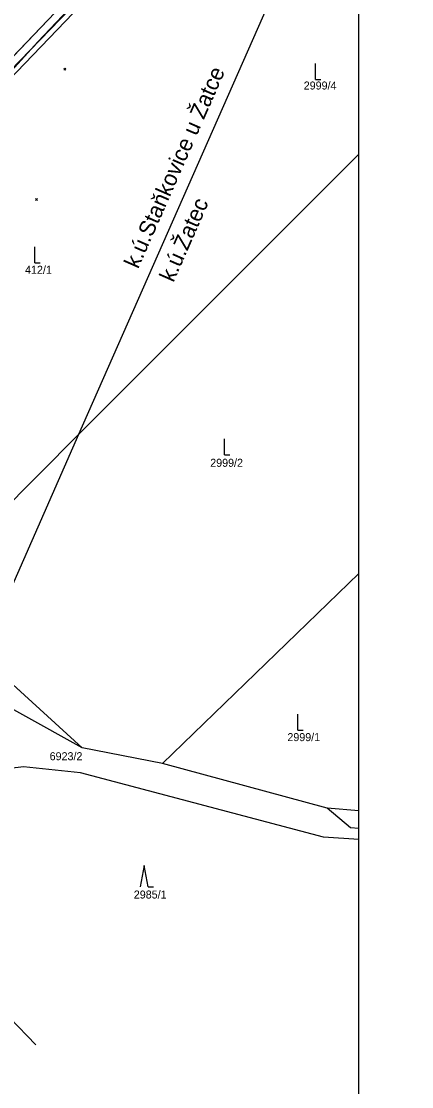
# Model space of a CAD drawing. Extents: x -800194 to -799078, y -1007177 to -1006597.
# Drawn here: x -799375.6 to -799302.5, y -1007052.9 to -1006853.3 of the extents above; entities that cross this region are included whole.
import ezdxf

# ---------------------------------------------------------------- set-up
doc = ezdxf.new("R2010")
doc.units = 0
for name, color, linetype in [('Legenda 1', 7, 'Continuous'), ('Vrstva 49', 7, 'Continuous'), ('Vrstva 53', 7, 'Continuous'), ('Vrstva 55', 7, 'Continuous'), ('Vrstva 57', 7, 'Continuous'), ('Vrstva 58', 7, 'Continuous')]:
    doc.layers.add(name, color=color, linetype=linetype)

msp = doc.modelspace()

# ---------------------------------------------------------------- linework, layer by layer
at = {"layer": 'Legenda 1'}
msp.add_lwpolyline([(-800193.4, -1007176.65), (-799312.4, -1007176.65), (-799312.4, -1006766.65), (-800193.4, -1006766.65)], close=True, dxfattribs=at)
at = {"layer": 'Vrstva 49'}
for p, q in [((-799367.64, -1006862.11), (-799367.29, -1006862.46)), ((-799367.64, -1006862.46), (-799367.29, -1006862.11)), ((-799372.92, -1006886.5), (-799372.57, -1006886.86)), ((-799372.92, -1006886.86), (-799372.57, -1006886.5))]:
    msp.add_line(p, q, dxfattribs=at)
msp.add_lwpolyline([(-799405.31, -1006888.8), (-799396.79, -1006882.07), (-799386.95, -1006872.93), (-799372.54, -1006857.15), (-799356.35, -1006840.04), (-799339.51, -1006822.21), (-799317.89, -1006801.14), (-799302.5, -1006781.46)], dxfattribs=at)
at = {"layer": 'Vrstva 53'}
msp.add_lwpolyline([(-799312.4, -1006791.98), (-799331.37, -1006811.87), (-799413.75, -1006898.23), (-799418.41, -1006902.53), (-799423.07, -1006906.83), (-799433.4, -1006916.39), (-799469.5, -1006946.86), (-799487.22, -1006958.47), (-799495.25, -1006963.74), (-799521.98, -1006977.8), (-799546.71, -1006987.83)], dxfattribs=at)
at = {"layer": 'Vrstva 55'}
for p, q in [((-799413.75, -1006898.23), (-799331.37, -1006811.87)), ((-799364.81, -1006930.69), (-799312.4, -1006878.2)), ((-799393.3, -1006959.22), (-799364.81, -1006930.69)), ((-799383.1, -1006972.22), (-799364.81, -1006930.69)), ((-799312.4, -1006956.76), (-799349.19, -1006992.39)), ((-799364.19, -1006989.42), (-799383.1, -1006972.22)), ((-799349.19, -1006992.39), (-799364.19, -1006989.42)), ((-799318.36, -1007000.74), (-799349.19, -1006992.39)), ((-799312.4, -1007001.25), (-799318.36, -1007000.74))]:
    msp.add_line(p, q, dxfattribs=at)
for points in [[(-799329.14, -1006812.3), (-799409.48, -1006895.36), (-799407.32, -1006903.81)], [(-799328.26, -1006812.47), (-799403.59, -1006891), (-799407.32, -1006903.81)], [(-799364.81, -1006930.69), (-799327.63, -1006846.25), (-799317.77, -1006827.17)], [(-799364.19, -1006989.42), (-799386.5, -1006977.04), (-799383.1, -1006972.22)], [(-799312.4, -1007006.62), (-799318.99, -1007006.15), (-799364.52, -1006994.13), (-799375.17, -1006992.97), (-799396.86, -1006995.59)], [(-799396.86, -1006995.59), (-799394.17, -1007010.32), (-799387.01, -1007026.98), (-799377.82, -1007039.94), (-799372.89, -1007045.05)], [(-799312.4, -1007004.53), (-799313.97, -1007004.43), (-799318.36, -1007000.74)]]:
    msp.add_lwpolyline(points, dxfattribs=at)
at = {"layer": 'Vrstva 58'}
for p, q in [((-799320.53, -1006864.22), (-799320.53, -1006861.22)), ((-799320.53, -1006864.22), (-799319.53, -1006864.22)), ((-799373.05, -1006898.58), (-799373.05, -1006895.58)), ((-799373.05, -1006898.58), (-799372.05, -1006898.58)), ((-799337.58, -1006934.56), (-799337.58, -1006931.56)), ((-799337.58, -1006934.56), (-799336.58, -1006934.56)), ((-799323.8, -1006986.09), (-799323.8, -1006983.09)), ((-799323.8, -1006986.09), (-799322.8, -1006986.09)), ((-799352.59, -1007011.5), (-799353.34, -1007015.5)), ((-799351.84, -1007015.5), (-799352.59, -1007011.5)), ((-799351.84, -1007015.5), (-799350.84, -1007015.5))]:
    msp.add_line(p, q, dxfattribs=at)

# ---------------------------------------------------------------- texts
at = {"layer": 'Vrstva 55'}
for s, p in [('k.ú.Staňkovice u Žatce', (-799353.73, -1006899.81)), ('k.ú.Žatec', (-799347.12, -1006902.36))]:
    msp.add_text(s, height=3, rotation=66.2843, dxfattribs=at).set_placement(p)
at = {"layer": 'Vrstva 57'}
for s, p in [('2999/4', (-799322.72, -1006866.09)), ('412/1', (-799374.91, -1006900.61)), ('2999/2', (-799340.23, -1006936.77)), ('2999/1', (-799325.78, -1006988.17)), ('6923/2', (-799370.3, -1006991.75)), ('2985/1', (-799354.54, -1007017.66))]:
    msp.add_text(s, height=1.5, dxfattribs=at).set_placement(p)

doc.saveas('drawing.dxf')
